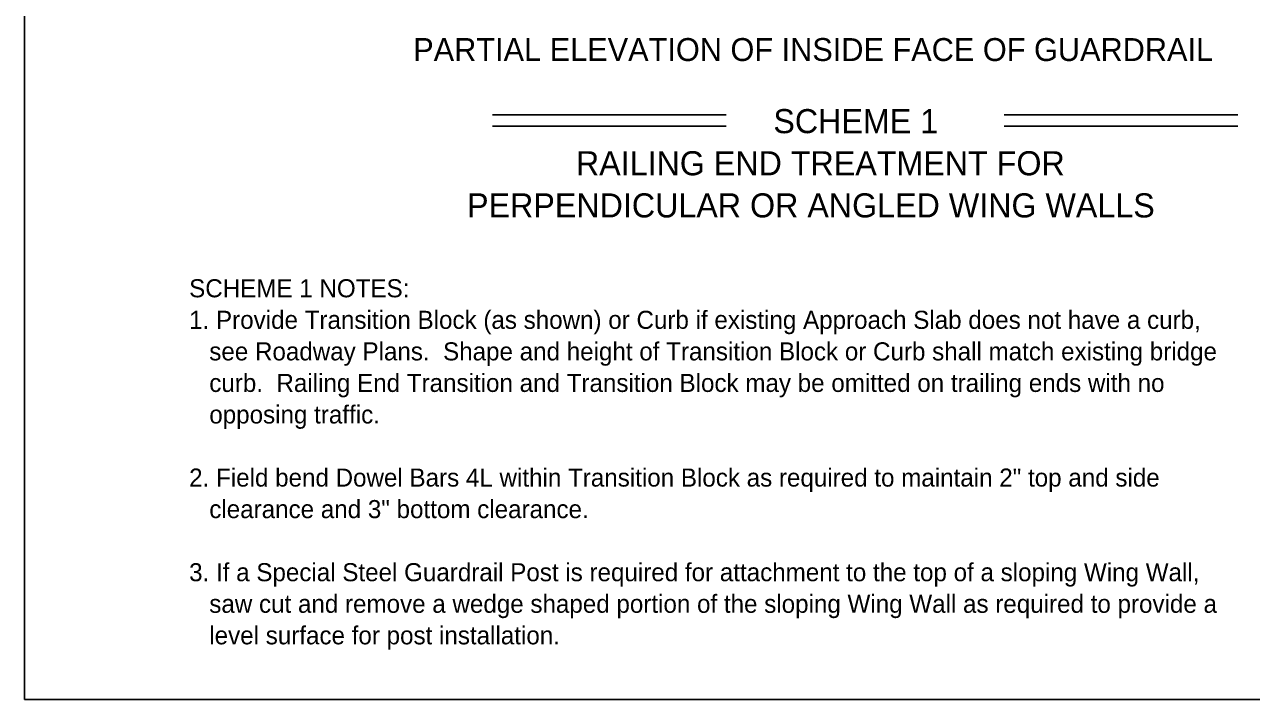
# Model space of a CAD drawing. Extents: x 0 to 41.1, y 0 to 26.
# Drawn here: x 0 to 13.68, y 0 to 7.53 of the extents above; entities that cross this region are included whole.
import ezdxf

# ---------------------------------------------------------------- set-up
doc = ezdxf.new("R2010")
doc.units = 0
for name, color, linetype in [('Dimension', 7, 'Continuous'), ('Miscellaneous1', 7, 'Continuous'), ('TextStructures', 7, 'Continuous')]:
    doc.layers.add(name, color=color, linetype=linetype)

msp = doc.modelspace()

# ---------------------------------------------------------------- linework, layer by layer
at = {"layer": 'Dimension'}
for p, q in [((7.825, 6.522), (5.218, 6.522)), ((10.926, 6.522), (13.533, 6.522)), ((7.825, 6.396), (5.218, 6.396)), ((10.926, 6.396), (13.533, 6.396))]:
    msp.add_line(p, q, dxfattribs=at)
msp.add_lwpolyline([(0, 0), (41.067, 0), (41.067, 25.97), (0, 25.97)], close=True, dxfattribs=at)
at = {"layer": 'Miscellaneous1'}
msp.add_lwpolyline([(0, 25.97), (41.067, 25.97), (41.067, 0), (0, 0)], close=True, dxfattribs=at)

# ---------------------------------------------------------------- texts
at = {"layer": 'Dimension'}
for s, height, p in [('SCHEME 1', 0.2688, (8.352, 6.318)), ('RAILING END TREATMENT FOR ', 0.2688, (6.15, 5.848)), ('PERPENDICULAR OR ANGLED WING WALLS', 0.2688, (4.936, 5.378)), ('SCHEME 1 NOTES:', 0.2016, (1.836, 4.487)), ('1. Provide Transition Block (as shown) or Curb if existing Approach Slab does not have a curb, ', 0.2016, (1.836, 4.135)), ('   see Roadway Plans.  Shape and height of Transition Block or Curb shall match existing bridge ', 0.2016, (1.836, 3.783)), ('   curb.  Railing End Transition and Transition Block may be omitted on trailing ends with no ', 0.2016, (1.836, 3.431)), ('   opposing traffic.', 0.2016, (1.836, 3.079)), ('2. Field bend Dowel Bars 4L within Transition Block as required to maintain 2" top and side ', 0.2016, (1.836, 2.375)), ('   clearance and 3" bottom clearance.   ', 0.2016, (1.836, 2.023)), ('3. If a Special Steel Guardrail Post is required for attachment to the top of a sloping Wing Wall, ', 0.2016, (1.836, 1.319)), ('   saw cut and remove a wedge shaped portion of the sloping Wing Wall as required to provide a ', 0.2016, (1.836, 0.967)), ('   level surface for post installation.', 0.2016, (1.836, 0.615))]:
    msp.add_text(s, height=height, dxfattribs=at).set_placement(p)
at = {"layer": 'TextStructures'}
msp.add_text('PARTIAL ELEVATION OF INSIDE FACE OF GUARDRAIL', height=0.256, dxfattribs=at).set_placement((4.335, 7.123))

doc.saveas('drawing.dxf')
